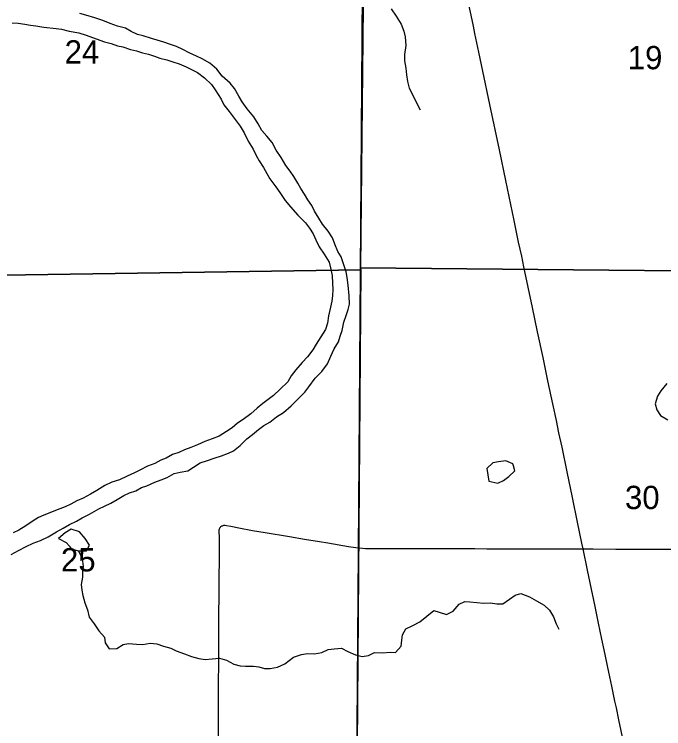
# Model space of a CAD drawing. Extents: x 0 to 34, y 0 to 22.
# Drawn here: x 5.138 to 5.721, y 14.991 to 15.634 of the extents above; entities that cross this region are included whole.
import ezdxf

# ---------------------------------------------------------------- set-up
doc = ezdxf.new("R2010")
doc.units = 0
for name, color, linetype in [('GM_X_County_Road', 7, 'Continuous'), ('GM_X_Major_River', 7, 'Continuous'), ('GM_X_Minor_Lake', 7, 'Continuous'), ('GM_X_Minor_River', 7, 'Continuous'), ('GM_X_Section', 7, 'Continuous'), ('GM_X_Section_Text', 7, 'Continuous'), ('GM_X_Township', 7, 'Continuous'), ('GM_X_Township_Road', 7, 'Continuous')]:
    doc.layers.add(name, color=color, linetype=linetype)

msp = doc.modelspace()

# ---------------------------------------------------------------- linework, layer by layer
at = {"layer": 'GM_X_County_Road'}
for points in [[(5.64859, 15.15296), (5.6475, 15.15821), (5.64354, 15.17706), (5.63894, 15.19927), (5.63416, 15.22241), (5.62958, 15.24431), (5.6268, 15.25738), (5.62448, 15.26833), (5.62127, 15.28353), (5.61688, 15.30421), (5.61253, 15.32521), (5.60768, 15.34801), (5.60312, 15.36992), (5.5954, 15.40673), (5.59337, 15.41615), (5.59055, 15.42889), (5.58657, 15.44837), (5.57914, 15.48429), (5.57337, 15.51167), (5.56477, 15.55242), (5.5584, 15.58252), (5.55485, 15.59956), (5.55131, 15.61628), (5.54992, 15.62297), (5.54792, 15.63272), (5.54413, 15.65067)], [(5.70076, 14.90079), (5.70074, 14.90198), (5.70026, 14.90634), (5.69966, 14.90972), (5.69791, 14.91795), (5.69712, 14.92159), (5.69449, 14.93406), (5.68736, 14.96685), (5.68265, 14.98936), (5.68059, 14.99941), (5.67838, 15.01006), (5.67708, 15.01613), (5.67422, 15.02949), (5.67157, 15.04226), (5.66742, 15.06235), (5.66544, 15.07179), (5.6624, 15.08607), (5.65928, 15.10129), (5.65486, 15.12259), (5.65257, 15.13386), (5.64859, 15.15296)]]:
    msp.add_lwpolyline(points, dxfattribs=at)
at = {"layer": 'GM_X_Major_River'}
for points in [[(5.38876, 15.48772), (5.38538, 15.49249), (5.38162, 15.49764), (5.37731, 15.50488), (5.37281, 15.51137), (5.36906, 15.51822), (5.36436, 15.52395), (5.35984, 15.5293), (5.35666, 15.5352), (5.35272, 15.5413), (5.3467, 15.54856), (5.34239, 15.55504), (5.33939, 15.56), (5.33545, 15.56705), (5.3315, 15.57182), (5.32434, 15.57795), (5.31964, 15.58424), (5.31323, 15.5898), (5.30624, 15.59364), (5.30132, 15.59596), (5.29451, 15.59885), (5.28884, 15.60193), (5.28317, 15.60482), (5.27787, 15.60638), (5.27181, 15.60851), (5.26595, 15.61026), (5.26084, 15.61201), (5.25345, 15.61415), (5.24815, 15.61552), (5.24267, 15.61822), (5.23737, 15.6211), (5.23018, 15.62306), (5.22374, 15.62538), (5.21712, 15.62809), (5.20993, 15.63042), (5.20179, 15.63276), (5.1963, 15.63432)], [(5.13571, 15.62586), (5.14102, 15.62563), (5.1469, 15.62482), (5.15202, 15.62383), (5.15675, 15.62323), (5.16414, 15.62204), (5.17514, 15.62081), (5.18007, 15.62021), (5.1867, 15.61845), (5.1956, 15.61687), (5.20223, 15.61492), (5.21112, 15.61144), (5.2185, 15.60891), (5.22456, 15.60735), (5.23024, 15.60541), (5.23516, 15.60424), (5.24179, 15.6021), (5.24728, 15.60073), (5.25258, 15.59898), (5.25808, 15.5978), (5.26337, 15.59586), (5.2683, 15.59431), (5.27454, 15.59255), (5.28004, 15.59099), (5.28552, 15.58906), (5.29196, 15.58654), (5.30216, 15.58134), (5.30839, 15.57655), (5.3148, 15.57062), (5.31799, 15.56585)], [(5.31799, 15.56585), (5.32343, 15.55727), (5.32586, 15.55232), (5.33056, 15.54622), (5.33507, 15.5403), (5.34052, 15.53305), (5.34408, 15.52695), (5.34763, 15.51952), (5.35213, 15.51247), (5.35475, 15.50676), (5.35737, 15.50181), (5.3615, 15.49589), (5.36431, 15.49056), (5.36712, 15.4856), (5.37238, 15.47836), (5.37595, 15.4734), (5.38101, 15.46615), (5.38553, 15.46061), (5.3923, 15.45297), (5.39909, 15.44628), (5.40265, 15.44132), (5.40603, 15.43617), (5.40846, 15.43084), (5.41145, 15.42456), (5.41596, 15.41807), (5.42027, 15.41064), (5.42156, 15.4057), (5.42302, 15.39867), (5.42354, 15.39183), (5.42369, 15.38614), (5.42327, 15.38083), (5.42267, 15.37571), (5.42149, 15.37041), (5.41992, 15.36245), (5.41892, 15.35601), (5.41717, 15.35014), (5.41295, 15.34372), (5.40873, 15.33711), (5.40584, 15.33182), (5.40105, 15.3256), (5.39627, 15.32051), (5.39053, 15.31391), (5.38632, 15.30863), (5.38325, 15.30334), (5.37637, 15.29656), (5.37045, 15.29092), (5.36568, 15.28735), (5.36072, 15.28378), (5.35575, 15.27964), (5.35003, 15.27456), (5.34316, 15.2693), (5.3382, 15.26593), (5.33324, 15.26179), (5.32828, 15.2586), (5.32161, 15.25429), (5.31533, 15.25187), (5.30867, 15.24945), (5.3022, 15.24666), (5.29611, 15.24405), (5.2904, 15.24219), (5.28526, 15.23976), (5.27975, 15.23772), (5.27403, 15.23454), (5.26908, 15.23268), (5.26375, 15.22968), (5.25709, 15.22727), (5.25043, 15.2239), (5.24567, 15.22147), (5.239, 15.21848), (5.23196, 15.21512), (5.22511, 15.2129), (5.21883, 15.20991), (5.21178, 15.20541), (5.20587, 15.20223), (5.1994, 15.19867), (5.19387, 15.19606), (5.18835, 15.19325), (5.18321, 15.19082), (5.17617, 15.18803), (5.16951, 15.18543), (5.16418, 15.18338), (5.15943, 15.18114), (5.15447, 15.17833), (5.1478, 15.17383), (5.14151, 15.16989), (5.13656, 15.16746)], [(5.13471, 15.14793), (5.14119, 15.15149), (5.14823, 15.15504), (5.15452, 15.15822), (5.16098, 15.16045), (5.16784, 15.16381), (5.17546, 15.16831), (5.18155, 15.17167), (5.18708, 15.17486), (5.19336, 15.17804), (5.19851, 15.18103), (5.20517, 15.18421), (5.21337, 15.18908), (5.21851, 15.19151), (5.22441, 15.19412), (5.22993, 15.19749), (5.23584, 15.20086), (5.24098, 15.20348), (5.24669, 15.20533), (5.25183, 15.20814), (5.25658, 15.20962), (5.26382, 15.21298), (5.26953, 15.21503), (5.27485, 15.21726), (5.28114, 15.22063), (5.28665, 15.22211), (5.29349, 15.2232), (5.29864, 15.22657), (5.30455, 15.23032), (5.31101, 15.23255), (5.3171, 15.23459), (5.32357, 15.23663), (5.32984, 15.23905), (5.33461, 15.24129), (5.34052, 15.24599), (5.34645, 15.25182), (5.3516, 15.25596), (5.35694, 15.26047), (5.36171, 15.26385), (5.36705, 15.26685), (5.37296, 15.27173), (5.37944, 15.27567), (5.38613, 15.28169), (5.39224, 15.28753), (5.39855, 15.29393), (5.40219, 15.29883), (5.40793, 15.30638), (5.41386, 15.31241), (5.41884, 15.31939), (5.42193, 15.32639), (5.42482, 15.33281), (5.42866, 15.33905), (5.43022, 15.34416), (5.43196, 15.34946), (5.43354, 15.35684), (5.43567, 15.36271), (5.43741, 15.3682), (5.43878, 15.37312), (5.43845, 15.38052), (5.43738, 15.39002), (5.43648, 15.39686), (5.43557, 15.40217), (5.43335, 15.40921), (5.43131, 15.41568), (5.42812, 15.42045), (5.42551, 15.42711), (5.42346, 15.43262), (5.41952, 15.43872), (5.41444, 15.44502), (5.41126, 15.45036), (5.40713, 15.45665), (5.4047, 15.4616), (5.40113, 15.46694), (5.39813, 15.4719), (5.39494, 15.47686), (5.39213, 15.48181), (5.38876, 15.48772)]]:
    msp.add_lwpolyline(points, dxfattribs=at)
at = {"layer": 'GM_X_Minor_Lake'}
for points in [[(5.58586, 15.22778), (5.58535, 15.22952), (5.5791, 15.23204), (5.57265, 15.23133), (5.56752, 15.23042), (5.56198, 15.22534), (5.56379, 15.21375)], [(5.56379, 15.21375), (5.57194, 15.21217), (5.57689, 15.2146), (5.58166, 15.21817), (5.5872, 15.22325), (5.58586, 15.22778)], [(5.20372, 15.15377), (5.20497, 15.15632), (5.20122, 15.16242), (5.19614, 15.16834), (5.18876, 15.17067), (5.18323, 15.16749), (5.17731, 15.16222)], [(5.17731, 15.16222), (5.18412, 15.15875), (5.18939, 15.15264), (5.19526, 15.15127), (5.20247, 15.15122), (5.20372, 15.15377)]]:
    msp.add_lwpolyline(points, dxfattribs=at)
at = {"layer": 'GM_X_Minor_River'}
for points in [[(5.47619, 15.63846), (5.48069, 15.63198), (5.48519, 15.62473), (5.48742, 15.61846), (5.48853, 15.61351), (5.48942, 15.60554), (5.48803, 15.59758), (5.48799, 15.59189), (5.48927, 15.58505), (5.48999, 15.57935), (5.49089, 15.57308), (5.49236, 15.56719), (5.49517, 15.56148), (5.49891, 15.55405), (5.50228, 15.54776)], [(5.72381, 15.30171), (5.71826, 15.29512), (5.71538, 15.2902), (5.71324, 15.28339), (5.71471, 15.27788), (5.7179, 15.27292), (5.72452, 15.26908)], [(5.19526, 15.15127), (5.19862, 15.14422), (5.19952, 15.1372), (5.19891, 15.13227), (5.19869, 15.12753), (5.19769, 15.12108), (5.19823, 15.11596), (5.19914, 15.11102), (5.2008, 15.10436), (5.20322, 15.09809), (5.20469, 15.09162), (5.20939, 15.08571), (5.21352, 15.07941), (5.2186, 15.07349), (5.21913, 15.06856), (5.22289, 15.06303), (5.22953, 15.06355), (5.23544, 15.06711), (5.24019, 15.06802), (5.24739, 15.06721), (5.25289, 15.06697), (5.25973, 15.06825), (5.26561, 15.06764), (5.27167, 15.0655), (5.2781, 15.06375), (5.28302, 15.06124), (5.29059, 15.05853), (5.29664, 15.0564), (5.30327, 15.05445), (5.30915, 15.05365), (5.31541, 15.05417), (5.32187, 15.05469), (5.32811, 15.05293), (5.33473, 15.04928), (5.34041, 15.04772), (5.34534, 15.04768), (5.35236, 15.04744), (5.3571, 15.04683), (5.3624, 15.04546), (5.36734, 15.04543), (5.37398, 15.04671), (5.38046, 15.04969), (5.38847, 15.0557), (5.39551, 15.05793), (5.40102, 15.05883), (5.40727, 15.0586), (5.41393, 15.05987), (5.41945, 15.06249), (5.42495, 15.06302), (5.43141, 15.06373), (5.43727, 15.06065), (5.44408, 15.05775), (5.44995, 15.05638), (5.45565, 15.05709), (5.46117, 15.05971), (5.46819, 15.05965), (5.47521, 15.06017), (5.47995, 15.05975), (5.48493, 15.0656), (5.48572, 15.0709), (5.48614, 15.07583), (5.48921, 15.08112), (5.4955, 15.08411), (5.50197, 15.08729), (5.50827, 15.09255), (5.51438, 15.09763), (5.5193, 15.09607), (5.52593, 15.09394), (5.53183, 15.09712), (5.53719, 15.10334), (5.54214, 15.10577), (5.54688, 15.10535), (5.55295, 15.10474), (5.5592, 15.10431), (5.56528, 15.10464), (5.57115, 15.10346), (5.57627, 15.10361), (5.58238, 15.10774), (5.58734, 15.1115), (5.59266, 15.11278), (5.60042, 15.10988), (5.60665, 15.10623), (5.61345, 15.10238), (5.61835, 15.09798), (5.62191, 15.09188), (5.62434, 15.0856), (5.62658, 15.08084)]]:
    msp.add_lwpolyline(points, dxfattribs=at)
at = {"layer": 'GM_X_Section'}
for points in [[(4.9508, 15.90083), (5.45367, 15.90574), (5.44855, 15.40559), (5.44873, 15.40388), (4.9466, 15.39652)], [(5.45367, 15.90574), (5.96256, 15.90376), (5.95855, 15.40077), (5.44855, 15.40559)], [(5.44873, 15.40388), (5.44507, 14.89729), (4.94245, 14.8996), (4.9466, 15.39652)], [(5.44873, 15.40388), (5.44855, 15.40559), (5.95855, 15.40077), (5.95095, 14.90007), (5.44507, 14.89729)]]:
    msp.add_lwpolyline(points, close=True, dxfattribs=at)
at = {"layer": 'GM_X_Township'}
for points in [[(3.86539, 14.40349), (4.43815, 14.40265), (5.04041, 14.40177), (5.06657, 14.40173), (5.44111, 14.40116), (5.44669, 15.15063), (5.45044, 15.65487), (5.45419, 15.90393), (5.45428, 16.08137), (5.45292, 16.19179), (5.45515, 16.40295), (5.45701, 16.6786), (5.45812, 16.85635), (5.46352, 17.41199), (4.99421, 17.40763), (4.77846, 17.40425), (4.32513, 17.40324)], [(7.45459, 14.40015), (7.13726, 14.39886), (6.95145, 14.39952), (6.83768, 14.39906), (6.14063, 14.40011), (5.94628, 14.40039), (5.52367, 14.40104), (5.44111, 14.40116), (5.44669, 15.15063), (5.45044, 15.65487), (5.45419, 15.90393), (5.45428, 16.08137), (5.45292, 16.19179), (5.45515, 16.40295), (5.45701, 16.6786), (5.45812, 16.85635), (5.46352, 17.41199)]]:
    msp.add_lwpolyline(points, dxfattribs=at)
at = {"layer": 'GM_X_Township_Road'}
for points in [[(5.32105, 14.98202), (5.32096, 15.01422), (5.32092, 15.0223), (5.32097, 15.03039), (5.32128, 15.05213), (5.3214, 15.06828), (5.32137, 15.07635), (5.32138, 15.08194), (5.32141, 15.08629), (5.3214, 15.09094), (5.32141, 15.0956), (5.32143, 15.10057), (5.32145, 15.10461), (5.32156, 15.11518), (5.32162, 15.12169), (5.32172, 15.13375), (5.32174, 15.13652), (5.32177, 15.13993), (5.32186, 15.14643), (5.32193, 15.15077), (5.32192, 15.15262), (5.32193, 15.15853), (5.32182, 15.16346), (5.32167, 15.16875), (5.3217, 15.16959), (5.32173, 15.17028), (5.32187, 15.17097), (5.32204, 15.17152), (5.32231, 15.17195), (5.32259, 15.17235), (5.32288, 15.17267), (5.32323, 15.17302), (5.3236, 15.1733), (5.32406, 15.17359), (5.32447, 15.1738)], [(5.32447, 15.1738), (5.32517, 15.17409), (5.32585, 15.17426), (5.32645, 15.17431), (5.327, 15.17429), (5.32832, 15.17409), (5.33195, 15.17333), (5.33926, 15.17186), (5.35148, 15.16955), (5.36282, 15.16772), (5.3849, 15.16413), (5.39838, 15.16186), (5.41184, 15.15954), (5.41919, 15.15831), (5.43788, 15.15519), (5.44435, 15.15429), (5.44762, 15.15395)], [(5.44762, 15.15395), (5.45022, 15.15368), (5.453, 15.15349), (5.45797, 15.15329), (5.4581, 15.15329)], [(5.4581, 15.15329), (5.46512, 15.15325), (5.48096, 15.1533), (5.48935, 15.15334), (5.51763, 15.15323), (5.53162, 15.15326), (5.54404, 15.15325), (5.55119, 15.15322), (5.56207, 15.15317), (5.57481, 15.1531), (5.59189, 15.15301), (5.60556, 15.15296), (5.61613, 15.15294), (5.62981, 15.15297), (5.64317, 15.15299), (5.64859, 15.15296)], [(5.64859, 15.15296), (5.65747, 15.15292), (5.67798, 15.15287), (5.69539, 15.15286), (5.70378, 15.15285), (5.71496, 15.15281), (5.72988, 15.15275), (5.76034, 15.1525), (5.77961, 15.1524), (5.79702, 15.15228), (5.81131, 15.15217), (5.8225, 15.15208), (5.8312, 15.15199), (5.84019, 15.1519), (5.84578, 15.15185), (5.86473, 15.15185), (5.8756, 15.15185), (5.8846, 15.15185), (5.89766, 15.15186), (5.91537, 15.15181), (5.93309, 15.15172), (5.95522, 15.15137)]]:
    msp.add_lwpolyline(points, dxfattribs=at)

# ---------------------------------------------------------------- texts
at = {"layer": 'GM_X_Section_Text'}
for s, p in [('24', (5.18278, 15.58936)), ('19', (5.68862, 15.58421)), ('30', (5.68612, 15.18879)), ('25', (5.17945, 15.13275))]:
    msp.add_text(s, height=0.020928, rotation=0.00001, dxfattribs=at).set_placement(p)

doc.saveas('drawing.dxf')
